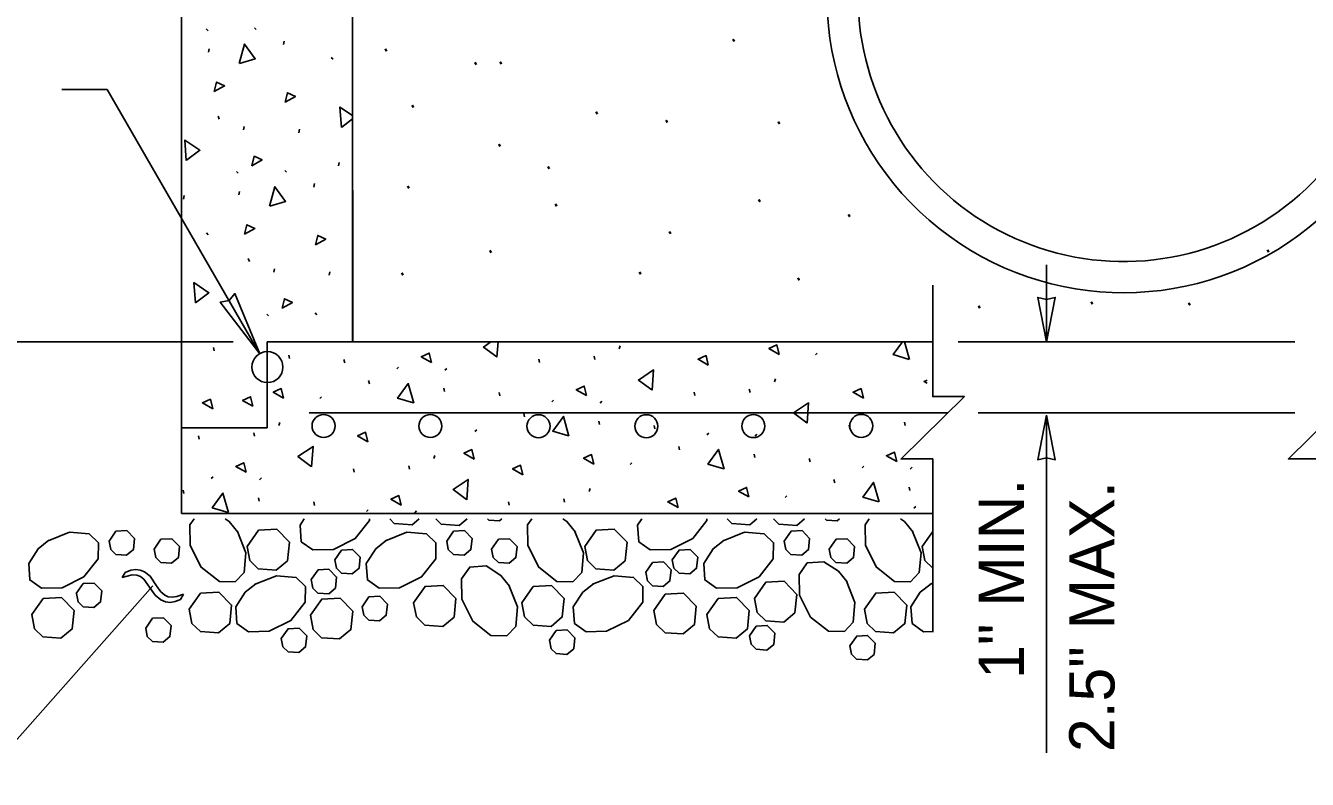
# Model space of a CAD drawing. Extents: x 99862 to 103151, y 100000 to 102076.
# Drawn here: x 100549.1 to 101001.8, y 100489.3 to 100755.3 of the extents above; entities that cross this region are included whole.
import ezdxf

# ---------------------------------------------------------------- set-up
doc = ezdxf.new("R2010")
doc.units = 0
for name, color, linetype in [('Level 1', 7, 'Continuous'), ('Level 13', 7, 'Continuous'), ('Level 15', 7, 'Continuous'), ('Level 16', 7, 'Continuous'), ('Level 17', 7, 'Continuous'), ('Level 18', 7, 'Continuous'), ('Level 19', 7, 'Continuous'), ('Level 20', 7, 'Continuous'), ('Level 23', 7, 'Continuous')]:
    doc.layers.add(name, color=color, linetype=linetype)

msp = doc.modelspace()

# ---------------------------------------------------------------- linework, layer by layer
at = {"layer": 'Level 1'}
msp.add_arc((100936.81, 100765.78), 104.72, 154.3283, 26.0354, dxfattribs=at)
at = {"layer": 'Level 13'}
msp.add_circle((100634.49, 100634.82), 5.48, dxfattribs=at)
at = {"layer": 'Level 15'}
for p, q in [((100561.94, 100732.76), (100577.94, 100732.76)), ((100631.75, 100639.56), (100577.94, 100732.76)), ((100909.65, 100643.69), (100909.65, 100670.96)), ((100622.4, 100643.69), (100352.49, 100643.69)), ((100878.43, 100643.69), (100997.29, 100643.69)), ((100885.47, 100618.69), (100997.29, 100618.69)), ((100909.65, 100498.68), (100909.65, 100617.82)), ((100583.17, 100560.51), (100584.23, 100562.34)), ((100586.75, 100561.44), (100583.17, 100560.51)), ((100584.23, 100562.34), (100586.24, 100563.09)), ((100586.24, 100563.09), (100588, 100563.36)), ((100588.39, 100561.39), (100586.75, 100561.44)), ((100588, 100563.36), (100589.61, 100563.18)), ((100589.73, 100560.91), (100588.39, 100561.39)), ((100589.61, 100563.18), (100591.14, 100562.53)), ((100590.89, 100559.96), (100589.73, 100560.91)), ((100592.28, 100557.97), (100590.89, 100559.96)), ((100591.14, 100562.53), (100593.06, 100560.99)), ((100593.06, 100560.99), (100595.33, 100557.59)), ((100593.98, 100557.57), (100533.48, 100489.28)), ((100594.8, 100554.35), (100592.28, 100557.97)), ((100595.33, 100557.59), (100596.8, 100555.5)), ((100596.8, 100555.5), (100598.25, 100554.25)), ((100602.55, 100553.87), (100604.86, 100554.61)), ((100604.86, 100554.61), (100603.81, 100552.78)), ((100596.88, 100552.6), (100594.8, 100554.35)), ((100598.51, 100551.92), (100596.88, 100552.6)), ((100598.25, 100554.25), (100599.49, 100553.75)), ((100600.2, 100551.72), (100598.51, 100551.92)), ((100599.49, 100553.75), (100600.84, 100553.6)), ((100601.97, 100552.01), (100600.2, 100551.72)), ((100600.84, 100553.6), (100602.55, 100553.87)), ((100603.81, 100552.78), (100601.97, 100552.01))]:
    msp.add_line(p, q, dxfattribs=at)
for points in [[(100869.47, 100663.69), (100869.47, 100624.41), (100880.67, 100624.41), (100858.27, 100602.42), (100869.47, 100602.42), (100869.47, 100541.28)], [(101006.25, 100663.69), (101006.25, 100624.41), (101017.45, 100624.41), (100995.05, 100602.42), (101006.25, 100602.42), (101006.25, 100515.14)]]:
    msp.add_lwpolyline(points, dxfattribs=at)
for points in [[(100631.84, 100639.49), (100617.84, 100657.77), (100620.95, 100658.35), (100623.01, 100660.75)], [(100909.65, 100643.69), (100906.57, 100659.42), (100909.65, 100658.69), (100912.74, 100659.42)], [(100909.65, 100617.82), (100906.57, 100602.09), (100909.65, 100602.82), (100912.74, 100602.09)]]:
    msp.add_lwpolyline(points, close=True, dxfattribs=at)
at = {"layer": 'Level 16'}
for p, q in [((100612.88, 100754.18), (100613.52, 100753.56)), ((100629.91, 100754.57), (100630.55, 100753.95)), ((100640.21, 100748.69), (100640.46, 100749.89)), ((100613.66, 100745.97), (100613.91, 100747.17)), ((100657.06, 100744.14), (100657.7, 100743.52)), ((100617.06, 100723.45), (100617.41, 100722.38)), ((100626.01, 100718.61), (100626.26, 100719.8)), ((100645.55, 100717.55), (100645.81, 100718.75)), ((100623.57, 100703.86), (100624.21, 100703.23)), ((100640.61, 100704.24), (100641.25, 100703.62)), ((100659.62, 100705.8), (100659.87, 100707)), ((100650.9, 100698.37), (100651.16, 100699.57)), ((100604.84, 100694.15), (100605.1, 100695.35)), ((100624.35, 100695.65), (100624.61, 100696.85)), ((100612.98, 100682.17), (100613.62, 100681.55)), ((100627.75, 100673.12), (100628.11, 100672.05)), ((100636.71, 100668.28), (100636.96, 100669.48)), ((100656.25, 100667.22), (100656.51, 100668.42)), ((100634.27, 100653.53), (100634.91, 100652.9)), ((100651.31, 100653.91), (100651.95, 100653.29)), ((100615.73, 100640.53), (100615.47, 100641.73)), ((100759.13, 100642.33), (100758.77, 100641.26)), ((100642.28, 100637.81), (100642.02, 100639.01)), ((100661.79, 100636.32), (100661.53, 100637.51)), ((100730.63, 100636.43), (100730.37, 100637.62)), ((100750.17, 100637.48), (100749.92, 100638.68)), ((100828.67, 100639.73), (100828.03, 100639.11)), ((100680.8, 100634.76), (100680.16, 100634.14)), ((100697.83, 100634.37), (100697.19, 100633.75)), ((100670.5, 100628.89), (100670.25, 100630.08)), ((100697.05, 100626.17), (100696.8, 100627.36)), ((100804.95, 100625.84), (100804.69, 100627.04)), ((100813.9, 100630.68), (100813.55, 100629.61)), ((100653.65, 100624.33), (100653.01, 100623.71)), ((100716.57, 100624.67), (100716.31, 100625.87)), ((100735.57, 100623.12), (100734.93, 100622.49)), ((100752.61, 100622.73), (100751.97, 100622.11)), ((100785.4, 100624.78), (100785.15, 100625.98)), ((100725.28, 100617.24), (100725.03, 100618.44)), ((100638.88, 100615.28), (100638.52, 100614.21)), ((100751.83, 100614.52), (100751.57, 100615.72)), ((100771.34, 100613.03), (100771.09, 100614.23)), ((100840.18, 100613.14), (100839.92, 100614.34)), ((100859.72, 100614.19), (100859.47, 100615.39)), ((100610.38, 100609.38), (100610.12, 100610.58)), ((100629.92, 100610.44), (100629.67, 100611.64)), ((100708.42, 100612.69), (100707.78, 100612.07)), ((100790.35, 100611.47), (100789.71, 100610.85)), ((100807.39, 100611.09), (100806.75, 100610.46)), ((100780.06, 100605.6), (100779.8, 100606.8)), ((100684.7, 100598.8), (100684.44, 100600)), ((100693.65, 100603.64), (100693.3, 100602.57)), ((100763.2, 100601.05), (100762.56, 100600.42)), ((100806.61, 100602.88), (100806.35, 100604.08)), ((100826.12, 100601.39), (100825.86, 100602.59)), ((100845.13, 100599.83), (100844.49, 100599.21)), ((100615.32, 100596.08), (100614.68, 100595.45)), ((100632.36, 100595.69), (100631.72, 100595.07)), ((100665.15, 100597.74), (100664.9, 100598.94)), ((100834.83, 100593.96), (100834.58, 100595.15)), ((100862.16, 100599.45), (100861.52, 100598.82)), ((100605.03, 100590.2), (100604.78, 100591.4)), ((100748.43, 100592), (100748.07, 100590.93)), ((100861.38, 100591.24), (100861.13, 100592.44)), ((100631.58, 100587.48), (100631.32, 100588.68)), ((100651.09, 100585.99), (100650.84, 100587.19)), ((100719.93, 100586.1), (100719.67, 100587.3)), ((100739.47, 100587.15), (100739.22, 100588.35)), ((100817.98, 100589.4), (100817.34, 100588.78)), ((100670.1, 100584.43), (100669.46, 100583.81)), ((100687.14, 100584.05), (100686.5, 100583.42))]:
    msp.add_line(p, q, dxfattribs=at)
for points in [[(100624.49, 100741.93), (100626.45, 100748.82), (100630.22, 100743.65), (100624.61, 100741.95)], [(100615.73, 100732.05), (100616.54, 100735.4), (100619.36, 100734.1), (100615.73, 100732.05)], [(100640.76, 100728.29), (100641.57, 100731.64), (100644.39, 100730.33), (100640.76, 100728.29)], [(100660.62, 100719.44), (100660.1, 100726.59), (100664.59, 100723.57)], [(100664.59, 100722.4), (100660.72, 100719.5)], [(100605.84, 100707.8), (100605.33, 100714.95), (100610.64, 100711.38), (100605.95, 100707.86)], [(100628.97, 100705.89), (100629.78, 100709.24), (100632.6, 100707.93), (100628.97, 100705.89)], [(100635.18, 100691.6), (100637.15, 100698.49), (100640.92, 100693.32), (100635.31, 100691.62)], [(100626.43, 100681.73), (100627.23, 100685.07), (100630.06, 100683.77), (100626.43, 100681.73)], [(100651.46, 100677.96), (100652.27, 100681.31), (100655.09, 100680), (100651.46, 100677.96)], [(100609.04, 100657.47), (100608.53, 100664.62), (100613.84, 100661.05), (100609.15, 100657.53)], [(100639.67, 100655.56), (100640.48, 100658.91), (100643.3, 100657.61), (100639.67, 100655.56)], [(100713.44, 100643.69), (100710.77, 100641.89), (100715.46, 100638.38)], [(100715.57, 100638.31), (100715.95, 100643.69)], [(100815.23, 100639.29), (100814.42, 100642.63), (100811.6, 100641.33), (100815.23, 100639.29)], [(100858.76, 100643.69), (100855.51, 100639.24), (100861.13, 100637.54)], [(100861.25, 100637.52), (100859.49, 100643.69)], [(100692.44, 100636.41), (100691.63, 100639.76), (100688.8, 100638.45), (100692.44, 100636.41)], [(100790.2, 100635.52), (100789.39, 100638.87), (100786.57, 100637.56), (100790.2, 100635.52)], [(100770.34, 100626.67), (100770.85, 100633.82), (100765.54, 100630.25), (100770.24, 100626.73)], [(100640.21, 100623.89), (100639.4, 100627.24), (100636.58, 100625.93), (100640.21, 100623.89)], [(100686.22, 100622.12), (100684.26, 100629.01), (100680.49, 100623.84), (100686.1, 100622.14)], [(100747.21, 100624.77), (100746.4, 100628.12), (100743.58, 100626.81), (100747.21, 100624.77)], [(100844.98, 100623.88), (100844.16, 100627.23), (100841.35, 100625.92), (100844.98, 100623.88)], [(100867.46, 100630.19), (100866.38, 100629.69), (100867.46, 100629.08)], [(100615.18, 100620.12), (100614.36, 100623.47), (100611.55, 100622.16), (100615.18, 100620.12)], [(100629.36, 100620.99), (100628.55, 100624.34), (100625.73, 100623.03), (100629.36, 100620.99)], [(100825.12, 100615.03), (100825.63, 100622.18), (100820.32, 100618.61), (100825.01, 100615.09)], [(100741, 100610.47), (100739.03, 100617.37), (100735.26, 100612.2), (100740.88, 100610.5)], [(100669.95, 100608.48), (100669.14, 100611.83), (100666.32, 100610.52), (100669.95, 100608.48)], [(100650.09, 100599.63), (100650.6, 100606.78), (100645.29, 100603.21), (100649.99, 100599.69)], [(100707.55, 100602.33), (100706.74, 100605.68), (100703.92, 100604.37), (100707.55, 100602.33)], [(100795.78, 100598.83), (100793.81, 100605.73), (100790.04, 100600.56), (100795.65, 100598.86)], [(100856.77, 100601.48), (100855.95, 100604.83), (100853.13, 100603.52), (100856.77, 100601.48)], [(100626.96, 100597.72), (100626.15, 100601.07), (100623.33, 100599.77), (100626.96, 100597.72)], [(100724.73, 100596.83), (100723.91, 100600.18), (100721.1, 100598.88), (100724.73, 100596.83)], [(100749.76, 100600.6), (100748.95, 100603.95), (100746.13, 100602.64), (100749.76, 100600.6)], [(100704.87, 100587.99), (100705.38, 100595.14), (100700.07, 100591.57), (100704.76, 100588.05)], [(100804.53, 100588.96), (100803.73, 100592.31), (100800.9, 100591), (100804.53, 100588.96)], [(100850.55, 100587.19), (100848.59, 100594.08), (100844.82, 100588.91), (100850.43, 100587.21)], [(100620.75, 100583.43), (100618.78, 100590.33), (100615.01, 100585.16), (100620.63, 100583.46)], [(100681.74, 100586.08), (100680.93, 100589.43), (100678.11, 100588.13), (100681.74, 100586.08)], [(100779.5, 100585.19), (100778.69, 100588.54), (100775.87, 100587.24), (100779.5, 100585.19)]]:
    msp.add_lwpolyline(points, dxfattribs=at)
at = {"layer": 'Level 17'}
for p, q in [((100604.12, 100643.69), (100604.12, 101611.69)), ((100664.59, 100643.69), (100664.59, 101551.14)), ((100604.12, 100583.14), (100604.12, 100697.31)), ((100664.68, 100643.69), (100664.68, 100697.31)), ((100664.68, 100643.69), (100634.4, 100643.69)), ((100634.4, 100643.69), (100634.4, 100613.41)), ((100869.47, 100643.69), (100664.68, 100643.69)), ((100634.4, 100613.41), (100604.12, 100613.41)), ((100869.47, 100583.14), (100604.12, 100583.14))]:
    msp.add_line(p, q, dxfattribs=at)
msp.add_arc((100936.81, 100765.78), 93.72, 178.2436, 3.5092, dxfattribs=at)
at = {"layer": 'Level 18'}
msp.add_line((100874.85, 100618.69), (100649.22, 100618.69), dxfattribs=at)
for centre in [(100654.33, 100614.02), (100692.04, 100614.01), (100730.23, 100613.94), (100768.33, 100613.94), (100806.11, 100614), (100844.23, 100614.06)]:
    msp.add_circle(centre, 4.07, dxfattribs=at)
at = {"layer": 'Level 19'}
msp.add_line((100863.47, 100585.55), (100862.75, 100585.02), dxfattribs=at)
at = {"layer": 'Level 23'}
for p, q in [((100865.76, 100571.5), (100869.47, 100576.78)), ((100868.58, 100558.16), (100869.47, 100558.51))]:
    msp.add_line(p, q, dxfattribs=at)
for points in [[(100578.58, 100573.41), (100581, 100576.85), (100584.86, 100577.07), (100587.55, 100574.29), (100587.16, 100570.38), (100584.77, 100568.4), (100580.96, 100568.68), (100579.16, 100570.42), (100578.58, 100573.41)], [(100623.88, 100576.81), (100626.88, 100569.26), (100626.28, 100562.33), (100623.15, 100559.03), (100617.52, 100559.14), (100611.13, 100564.14), (100607.27, 100571.87), (100607.14, 100579.15), (100608.61, 100581.23)], [(100619.61, 100581.23), (100621.04, 100580.31), (100624.08, 100576.5)], [(100627.31, 100571.5), (100631.35, 100577.24), (100637.79, 100577.6), (100642.27, 100572.96), (100641.62, 100566.46), (100637.64, 100563.15), (100631.28, 100563.61), (100628.29, 100566.51), (100627.32, 100571.5)], [(100670.52, 100581.23), (100670.5, 100580.64), (100665.5, 100574.25), (100657.78, 100570.39), (100650.49, 100570.26), (100646.39, 100573.17), (100646.01, 100578.97), (100647.45, 100581.23)], [(100688.12, 100581.23), (100685.66, 100579.18), (100679.3, 100579.64), (100677.67, 100581.23)], [(100705.01, 100581.23), (100702.25, 100578.94), (100695.9, 100579.4), (100694.01, 100581.23)], [(100697.8, 100573.41), (100700.22, 100576.85), (100704.08, 100577.07), (100706.77, 100574.29), (100706.38, 100570.38), (100703.99, 100568.4), (100700.18, 100568.68), (100698.38, 100570.42), (100697.8, 100573.41)], [(100717.34, 100581.23), (100716.48, 100580.51), (100712.66, 100580.78), (100712.2, 100581.23)], [(100743.11, 100576.81), (100746.1, 100569.26), (100745.5, 100562.33), (100742.37, 100559.03), (100736.74, 100559.14), (100730.35, 100564.14), (100726.49, 100571.87), (100726.36, 100579.15), (100727.84, 100581.23)], [(100738.84, 100581.23), (100740.26, 100580.31), (100743.3, 100576.5)], [(100746.54, 100571.5), (100750.57, 100577.24), (100757.01, 100577.6), (100761.49, 100572.96), (100760.84, 100566.46), (100756.86, 100563.15), (100750.5, 100563.61), (100747.51, 100566.51), (100746.54, 100571.5)], [(100789.74, 100581.23), (100789.73, 100580.64), (100784.73, 100574.25), (100777, 100570.39), (100769.72, 100570.26), (100765.62, 100573.17), (100765.23, 100578.97), (100766.67, 100581.23)], [(100807.34, 100581.23), (100804.88, 100579.18), (100798.53, 100579.64), (100796.89, 100581.23)], [(100824.23, 100581.23), (100821.48, 100578.94), (100815.12, 100579.4), (100813.23, 100581.23)], [(100817.02, 100573.41), (100819.44, 100576.85), (100823.31, 100577.07), (100825.99, 100574.29), (100825.6, 100570.38), (100823.22, 100568.4), (100819.4, 100568.68), (100817.61, 100570.42), (100817.02, 100573.41)], [(100836.57, 100581.23), (100835.7, 100580.51), (100831.89, 100580.78), (100831.43, 100581.23)], [(100862.33, 100576.81), (100865.32, 100569.26), (100864.72, 100562.33), (100861.59, 100559.03), (100855.97, 100559.14), (100849.57, 100564.14), (100845.71, 100571.87), (100845.58, 100579.15), (100847.06, 100581.23)], [(100858.06, 100581.23), (100859.48, 100580.31), (100862.52, 100576.5)], [(100557.02, 100573.53), (100564.57, 100576.52), (100571.5, 100575.92), (100574.8, 100572.79), (100574.69, 100567.16), (100569.69, 100560.77), (100561.97, 100556.91), (100554.68, 100556.78), (100550.58, 100559.69), (100550.2, 100565.49), (100553.52, 100570.68), (100557.33, 100573.72)], [(100594.46, 100570.57), (100596.89, 100574.01), (100600.75, 100574.24), (100603.44, 100571.45), (100603.05, 100567.55), (100600.66, 100565.56), (100596.85, 100565.84), (100595.05, 100567.58), (100594.47, 100570.57)], [(100676.25, 100573.53), (100683.79, 100576.52), (100690.72, 100575.92), (100694.02, 100572.79), (100693.92, 100567.16), (100688.92, 100560.77), (100681.19, 100556.91), (100673.91, 100556.78), (100669.81, 100559.69), (100669.42, 100565.49), (100672.74, 100570.68), (100676.55, 100573.72)], [(100713.69, 100570.57), (100716.11, 100574.01), (100719.97, 100574.24), (100722.66, 100571.45), (100722.27, 100567.55), (100719.88, 100565.56), (100716.07, 100565.84), (100714.27, 100567.58), (100713.69, 100570.57)], [(100795.47, 100573.53), (100803.02, 100576.52), (100809.95, 100575.92), (100813.24, 100572.79), (100813.14, 100567.16), (100808.14, 100560.77), (100800.41, 100556.91), (100793.13, 100556.78), (100789.03, 100559.69), (100788.64, 100565.49), (100791.96, 100570.68), (100795.77, 100573.72)], [(100832.91, 100570.57), (100835.33, 100574.01), (100839.19, 100574.24), (100841.88, 100571.45), (100841.49, 100567.55), (100839.11, 100565.56), (100835.29, 100565.84), (100833.49, 100567.58), (100832.91, 100570.57)], [(100658.27, 100566.79), (100660.69, 100570.23), (100664.55, 100570.45), (100667.24, 100567.67), (100666.85, 100563.77), (100664.46, 100561.78), (100660.65, 100562.06), (100658.85, 100563.8), (100658.27, 100566.79)], [(100777.49, 100566.79), (100779.91, 100570.23), (100783.77, 100570.45), (100786.46, 100567.67), (100786.07, 100563.77), (100783.68, 100561.78), (100779.87, 100562.06), (100778.07, 100563.8), (100777.49, 100566.79)], [(100869.47, 100563.85), (100866.73, 100566.51), (100865.76, 100571.5)], [(100649.95, 100559.79), (100652.37, 100563.23), (100656.23, 100563.45), (100658.92, 100560.67), (100658.53, 100556.77), (100656.14, 100554.78), (100652.32, 100555.06), (100650.53, 100556.8), (100649.95, 100559.79)], [(100719.78, 100557.77), (100722.78, 100550.23), (100722.18, 100543.29), (100719.04, 100540), (100713.42, 100540.1), (100707.03, 100545.11), (100703.17, 100552.83), (100703.04, 100560.11), (100705.95, 100564.22), (100711.75, 100564.6), (100716.94, 100561.28), (100719.98, 100557.47)], [(100768.08, 100562.36), (100770.5, 100565.81), (100774.37, 100566.02), (100777.05, 100563.24), (100776.66, 100559.34), (100774.28, 100557.35), (100770.46, 100557.63), (100768.67, 100559.37), (100768.08, 100562.36)], [(100839, 100559.25), (100842, 100551.7), (100841.4, 100544.77), (100838.27, 100541.48), (100832.64, 100541.58), (100826.25, 100546.58), (100822.39, 100554.31), (100822.26, 100561.59), (100825.17, 100565.69), (100830.97, 100566.08), (100836.16, 100562.76), (100839.2, 100558.95)], [(100630.13, 100558.16), (100637.68, 100561.15), (100644.61, 100560.55), (100647.91, 100557.41), (100647.8, 100551.79), (100642.8, 100545.4), (100635.07, 100541.54), (100627.79, 100541.41), (100623.69, 100544.32), (100623.3, 100550.12), (100626.63, 100555.31), (100630.44, 100558.35)], [(100749.36, 100558.16), (100756.9, 100561.15), (100763.83, 100560.55), (100767.13, 100557.41), (100767.02, 100551.79), (100762.02, 100545.4), (100754.3, 100541.54), (100747.01, 100541.41), (100742.91, 100544.32), (100742.52, 100550.12), (100745.85, 100555.31), (100749.66, 100558.35)], [(100806.49, 100553.12), (100810.52, 100558.86), (100816.97, 100559.23), (100821.44, 100554.59), (100820.8, 100548.08), (100816.82, 100544.77), (100810.46, 100545.24), (100807.47, 100548.14), (100806.5, 100553.12)], [(100567.01, 100554.93), (100569.44, 100558.37), (100573.3, 100558.59), (100575.98, 100555.81), (100575.6, 100551.91), (100573.21, 100549.92), (100569.39, 100550.2), (100567.6, 100551.94), (100567.02, 100554.93)], [(100606.87, 100549.31), (100610.91, 100555.05), (100617.35, 100555.41), (100621.82, 100550.77), (100621.18, 100544.27), (100617.2, 100540.96), (100610.84, 100541.42), (100607.85, 100544.32), (100606.88, 100549.31)], [(100686.13, 100551.62), (100690.16, 100557.36), (100696.6, 100557.73), (100701.08, 100553.09), (100700.44, 100546.58), (100696.45, 100543.28), (100690.1, 100543.74), (100687.11, 100546.64), (100686.13, 100551.62)], [(100724.34, 100551.63), (100728.37, 100557.36), (100734.81, 100557.73), (100739.29, 100553.09), (100738.64, 100546.59), (100734.66, 100543.28), (100728.3, 100543.74), (100725.31, 100546.64), (100724.34, 100551.63)], [(100770.99, 100548.94), (100775.02, 100554.68), (100781.46, 100555.04), (100785.94, 100550.4), (100785.29, 100543.9), (100781.31, 100540.59), (100774.95, 100541.05), (100771.96, 100543.95), (100770.99, 100548.94)], [(100845.32, 100549.31), (100849.35, 100555.05), (100855.79, 100555.41), (100860.27, 100550.77), (100859.62, 100544.27), (100855.64, 100540.96), (100849.28, 100541.42), (100846.29, 100544.32), (100845.32, 100549.31)], [(100869.47, 100541.46), (100866.23, 100541.41), (100862.14, 100544.32), (100861.75, 100550.12), (100865.07, 100555.31), (100868.88, 100558.35)], [(100551.26, 100547.42), (100555.3, 100553.15), (100561.74, 100553.52), (100566.22, 100548.88), (100565.57, 100542.38), (100561.59, 100539.07), (100555.23, 100539.53), (100552.24, 100542.43), (100551.27, 100547.42)], [(100649.68, 100547.18), (100653.71, 100552.92), (100660.15, 100553.29), (100664.63, 100548.65), (100663.98, 100542.14), (100660, 100538.83), (100653.64, 100539.29), (100650.65, 100542.19), (100649.68, 100547.18)], [(100667.9, 100550.23), (100670.32, 100553.67), (100674.19, 100553.89), (100676.87, 100551.11), (100676.48, 100547.21), (100674.1, 100545.22), (100670.28, 100545.5), (100668.49, 100547.24), (100667.9, 100550.23)], [(100789.71, 100547.42), (100793.74, 100553.15), (100800.18, 100553.52), (100804.66, 100548.88), (100804.01, 100542.38), (100800.03, 100539.07), (100793.67, 100539.53), (100790.68, 100542.43), (100789.71, 100547.42)], [(100591.5, 100542.68), (100593.92, 100546.12), (100597.78, 100546.34), (100600.47, 100543.56), (100600.08, 100539.66), (100597.7, 100537.67), (100593.88, 100537.95), (100592.08, 100539.69), (100591.5, 100542.68)], [(100639.4, 100539.03), (100641.82, 100542.47), (100645.68, 100542.69), (100648.37, 100539.91), (100647.98, 100536.01), (100645.59, 100534.02), (100641.78, 100534.3), (100639.98, 100536.04), (100639.4, 100539.03)], [(100734.08, 100538.39), (100736.5, 100541.83), (100740.36, 100542.05), (100743.05, 100539.26), (100742.66, 100535.36), (100740.27, 100533.38), (100736.46, 100533.65), (100734.66, 100535.39), (100734.08, 100538.39)], [(100804.73, 100539.95), (100807.15, 100543.4), (100811.01, 100543.62), (100813.7, 100540.83), (100813.31, 100536.93), (100810.93, 100534.94), (100807.11, 100535.22), (100805.31, 100536.96), (100804.73, 100539.95)], [(100840.18, 100536.43), (100842.6, 100539.88), (100846.46, 100540.09), (100849.15, 100537.31), (100848.76, 100533.41), (100846.37, 100531.42), (100842.56, 100531.7), (100840.76, 100533.44), (100840.18, 100536.43)]]:
    msp.add_lwpolyline(points, dxfattribs=at)

# ---------------------------------------------------------------- texts
at = {"layer": 'Level 1'}
for p in [(100798.39, 100749.16), (100675.59, 100745.71), (100707.27, 100740.96), (100716.15, 100741.17), (100685.1, 100725.85), (100750.04, 100723.53), (100774.76, 100720.56), (100814.37, 100720.03), (100715.72, 100712.1), (100733.05, 100704.18), (100683.5, 100697.3), (100735.68, 100690.97), (100807.5, 100692.55), (100839.19, 100687.27), (100775.92, 100681.25), (100712.55, 100674.59), (100987.15, 100674.78), (100681.4, 100666.66), (100765.36, 100666.97), (100821.34, 100664.85), (100885.13, 100655.02), (100924.9, 100656.43), (100959.33, 100656.04)]:
    msp.add_text('.', height=6.3, rotation=30.9638, dxfattribs=at).set_placement(p)
at = {"layer": 'Level 20'}
for s, p in [(' 1" MIN.', (100901.65, 100518.81)), ('2.5" MAX.', (100933.65, 100498.91))]:
    msp.add_text(s, height=16, rotation=90, dxfattribs=at).set_placement(p)

doc.saveas('drawing.dxf')
